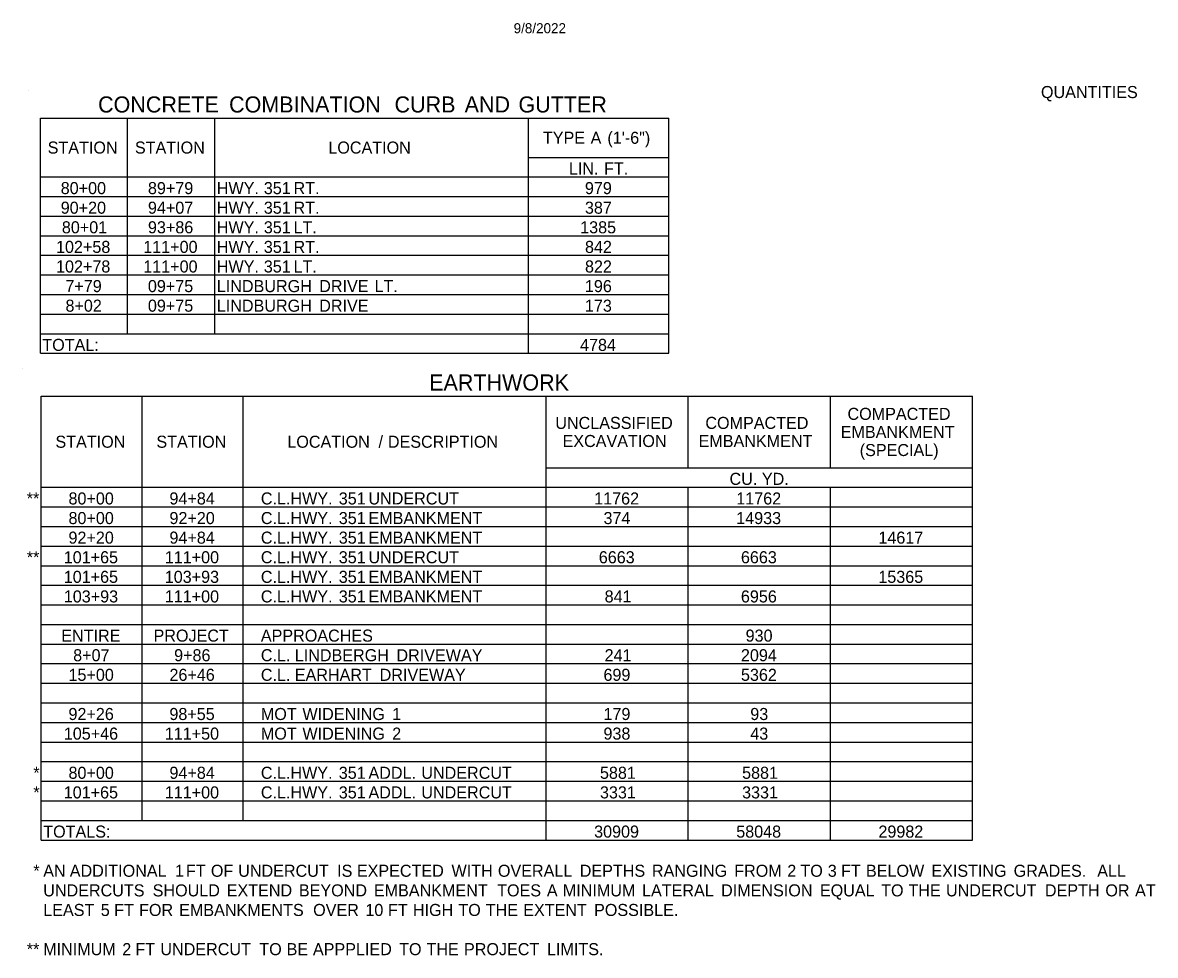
# Model space of a CAD drawing. Extents: x 1197542 to 1207068, y 230488 to 237324.
# Drawn here: x 1202654 to 1203218, y 232279 to 232744 of the extents above; entities that cross this region are included whole.
import ezdxf

# ---------------------------------------------------------------- set-up
doc = ezdxf.new("R2010")
doc.units = 0
doc.layers.add('Default', color=7, linetype='Continuous')
doc.layers.add('R_Border', color=7, linetype='Continuous')

msp = doc.modelspace()

# ---------------------------------------------------------------- linework, layer by layer
at = {"layer": 'Default'}
for p, q in [((1202657.22, 232709.68), (1202657.22, 232709.68)), ((1202663.07, 232696.03), (1202975.55, 232696.03)), ((1202663.07, 232579.03), (1202663.07, 232696.03)), ((1202663.07, 232579.03), (1202663.07, 232696.03)), ((1202706.45, 232588.78), (1202706.45, 232696.03)), ((1202749.84, 232588.78), (1202749.84, 232696.03)), ((1202905.84, 232579.03), (1202905.84, 232696.03)), ((1202975.55, 232579.03), (1202975.55, 232696.03)), ((1202905.84, 232676.53), (1202975.55, 232676.53)), ((1202663.07, 232666.78), (1202975.55, 232666.78)), ((1202706.45, 232588.78), (1202706.45, 232666.78)), ((1202749.84, 232588.78), (1202749.84, 232666.78)), ((1202905.84, 232666.78), (1202975.55, 232666.78)), ((1202905.84, 232579.03), (1202905.84, 232666.78)), ((1202663.07, 232657.03), (1202975.55, 232657.03)), ((1202749.84, 232657.03), (1202905.84, 232657.03)), ((1202663.07, 232647.28), (1202975.55, 232647.28)), ((1202663.07, 232637.53), (1202975.55, 232637.53)), ((1202663.07, 232627.78), (1202975.55, 232627.78)), ((1202663.07, 232618.03), (1202975.55, 232618.03)), ((1202663.07, 232608.28), (1202975.55, 232608.28)), ((1202663.07, 232598.53), (1202975.55, 232598.53)), ((1202663.07, 232588.78), (1202975.55, 232588.78)), ((1202975.55, 232579.03), (1202975.55, 232588.78)), ((1202663.07, 232579.03), (1202975.55, 232579.03)), ((1202654.25, 232571.35), (1202654.25, 232571.35)), ((1202663.52, 232557.7), (1203126.64, 232557.7)), ((1202663.52, 232336.86), (1202663.52, 232557.7)), ((1202663.52, 232336.86), (1202663.52, 232557.7)), ((1202713.73, 232346.61), (1202713.73, 232557.7)), ((1202763.94, 232346.61), (1202763.94, 232557.7)), ((1202914.58, 232336.86), (1202914.58, 232557.7)), ((1202985.27, 232522.11), (1202985.27, 232557.7)), ((1203055.95, 232522.11), (1203055.95, 232557.7)), ((1203126.64, 232336.86), (1203126.64, 232557.7)), ((1203126.64, 232336.86), (1203126.64, 232557.7)), ((1202914.58, 232522.11), (1203126.64, 232522.11)), ((1202663.52, 232512.36), (1203126.64, 232512.36)), ((1202713.73, 232346.61), (1202713.73, 232512.36)), ((1202763.94, 232502.61), (1202763.94, 232512.36)), ((1202914.58, 232502.61), (1202914.58, 232512.36)), ((1202985.27, 232336.86), (1202985.27, 232512.36)), ((1203055.95, 232336.86), (1203055.95, 232512.36)), ((1203055.95, 232346.61), (1203055.95, 232512.36)), ((1202663.52, 232502.61), (1203126.64, 232502.61)), ((1202663.52, 232492.86), (1203126.64, 232492.86)), ((1202663.52, 232483.11), (1203126.64, 232483.11)), ((1202763.94, 232346.61), (1202763.94, 232483.11)), ((1202914.58, 232375.86), (1202914.58, 232483.11)), ((1202663.52, 232473.36), (1203126.64, 232473.36)), ((1202663.52, 232463.61), (1203126.64, 232463.61)), ((1202663.52, 232453.86), (1203126.64, 232453.86)), ((1202663.52, 232444.11), (1203126.64, 232444.11)), ((1202663.52, 232434.36), (1203126.64, 232434.36)), ((1202663.52, 232424.61), (1203126.64, 232424.61)), ((1202663.52, 232414.86), (1203126.64, 232414.86)), ((1202663.52, 232405.11), (1203126.64, 232405.11)), ((1202663.52, 232395.36), (1203126.64, 232395.36)), ((1202663.52, 232385.61), (1203126.64, 232385.61)), ((1202663.52, 232375.86), (1203126.64, 232375.86)), ((1202713.73, 232375.86), (1202985.27, 232375.86)), ((1202985.27, 232375.86), (1203126.64, 232375.86)), ((1202663.52, 232366.11), (1203126.64, 232366.11)), ((1202663.52, 232356.36), (1203126.64, 232356.36)), ((1202914.58, 232346.61), (1202914.58, 232356.36)), ((1202663.52, 232346.61), (1202713.73, 232346.61)), ((1202663.52, 232346.61), (1203126.64, 232346.61)), ((1203055.95, 232346.61), (1203126.64, 232346.61)), ((1202663.52, 232336.86), (1203126.64, 232336.86))]:
    msp.add_line(p, q, dxfattribs=at)

# ---------------------------------------------------------------- texts
for s, height, p in [('CONCRETE', 8, (1202691.76, 232698.85)), (' COMBINATION', 8, (1202753.93, 232698.85)), (' CURB', 8, (1202836.24, 232698.85)), (' AND', 8, (1202871.09, 232698.85)), (' GUTTER', 8, (1202897.86, 232698.85)), ('TYPE', 6, (1202913.01, 232683.28)), (' A', 6, (1202934.49, 232683.28)), (' (1\'-6")', 6, (1202942.84, 232683.28)), ('STATION', 6, (1202666.7, 232678.4)), ('STATION', 6, (1202710.09, 232678.4)), ('LOCATION', 6, (1202806.29, 232678.4)), ('LIN.', 6, (1202925.91, 232667.98)), (' FT.', 6, (1202941.16, 232667.98)), ('80+00', 6, (1202673.19, 232658.23)), ('89+79', 6, (1202716.57, 232658.23)), ('HWY.', 6, (1202750.82, 232658.23)), (' 351', 6, (1202771.97, 232658.23)), (' RT.', 6, (1202786.74, 232658.23)), ('979', 6, (1202933.89, 232658.23)), ('90+20', 6, (1202673.19, 232648.48)), ('94+07', 6, (1202716.57, 232648.48)), ('HWY.', 6, (1202750.82, 232648.48)), (' 351', 6, (1202771.97, 232648.48)), (' RT.', 6, (1202786.74, 232648.48)), ('387', 6, (1202933.9, 232648.48)), ('80+01', 6, (1202673.76, 232638.73)), ('93+86', 6, (1202716.57, 232638.73)), ('HWY.', 6, (1202750.82, 232638.73)), (' 351', 6, (1202771.97, 232638.73)), (' LT.', 6, (1202786.74, 232638.73)), ('1385', 6, (1202931.54, 232638.73)), ('102+58', 6, (1202670.85, 232628.98)), ('111+00', 6, (1202714.25, 232628.98)), ('HWY.', 6, (1202750.82, 232628.98)), (' 351', 6, (1202771.97, 232628.98)), (' RT.', 6, (1202786.74, 232628.98)), ('842', 6, (1202933.93, 232628.98)), ('102+78', 6, (1202670.85, 232619.23)), ('111+00', 6, (1202714.25, 232619.23)), ('HWY.', 6, (1202750.82, 232619.23)), (' 351', 6, (1202771.97, 232619.23)), (' LT.', 6, (1202786.74, 232619.23)), ('822', 6, (1202933.93, 232619.23)), ('7+79', 6, (1202675.51, 232609.48)), ('09+75', 6, (1202716.55, 232609.48)), ('LINDBURGH', 6, (1202750.82, 232609.48)), (' DRIVE', 6, (1202799.52, 232609.48)), (' LT.', 6, (1202827.02, 232609.48)), ('196', 6, (1202933.9, 232609.48)), ('8+02', 6, (1202675.55, 232599.73)), ('09+75', 6, (1202716.55, 232599.73)), ('LINDBURGH', 6, (1202750.82, 232599.73)), (' DRIVE', 6, (1202799.52, 232599.73)), ('173', 6, (1202933.9, 232599.73)), ('TOTAL:', 6, (1202664.04, 232580.23)), ('4784', 6, (1202931.47, 232580.23)), ('EARTHWORK', 8, (1202856.43, 232560.52)), ('COMPACTED', 6, (1203064.49, 232545.9)), ('UNCLASSIFIED', 6, (1202919.16, 232541.4)), ('COMPACTED', 6, (1202993.8, 232541.4)), ('EMBANKMENT', 6, (1203061.11, 232536.9)), ('STATION', 6, (1202670.56, 232532.03)), ('STATION', 6, (1202720.77, 232532.03)), ('LOCATION', 6, (1202785.9, 232532.03)), (' /', 6, (1202829.01, 232532.03)), (' DESCRIPTION', 6, (1202833.67, 232532.03)), ('EXCAVATION', 6, (1202922.77, 232532.4)), ('EMBANKMENT', 6, (1202990.42, 232532.4)), ('(SPECIAL)', 6, (1203070.56, 232527.9)), ('CU.', 6, (1203005.82, 232513.56)), (' YD.', 6, (1203019.68, 232513.56)), ('**', 6, (1202656.31, 232503.81)), ('80+00', 6, (1202677.06, 232503.81)), ('94+84', 6, (1202727.27, 232503.81)), ('C.L.HWY.', 6, (1202772.72, 232503.81)), (' 351', 6, (1202809.24, 232503.81)), (' UNDERCUT', 6, (1202824.01, 232503.81)), ('11762', 6, (1202938.5, 232503.81)), ('11762', 6, (1203009.18, 232503.81)), ('80+00', 6, (1202677.06, 232494.06)), ('92+20', 6, (1202727.27, 232494.06)), ('C.L.HWY.', 6, (1202772.72, 232494.06)), (' 351', 6, (1202809.24, 232494.06)), (' EMBANKMENT', 6, (1202824.01, 232494.06)), ('374', 6, (1202943.14, 232494.06)), ('14933', 6, (1203009.15, 232494.06)), ('92+20', 6, (1202677.06, 232484.31)), ('94+84', 6, (1202727.27, 232484.31)), ('C.L.HWY.', 6, (1202772.72, 232484.31)), (' 351', 6, (1202809.24, 232484.31)), (' EMBANKMENT', 6, (1202824.01, 232484.31)), ('14617', 6, (1203079.84, 232484.31)), ('**', 6, (1202656.31, 232474.56)), ('101+65', 6, (1202674.69, 232474.56)), ('111+00', 6, (1202724.94, 232474.56)), ('C.L.HWY.', 6, (1202772.72, 232474.56)), (' 351', 6, (1202809.24, 232474.56)), (' UNDERCUT', 6, (1202824.01, 232474.56)), ('6663', 6, (1202940.79, 232474.56)), ('6663', 6, (1203011.48, 232474.56)), ('101+65', 6, (1202674.69, 232464.81)), ('103+93', 6, (1202724.93, 232464.81)), ('C.L.HWY.', 6, (1202772.72, 232464.81)), (' 351', 6, (1202809.24, 232464.81)), (' EMBANKMENT', 6, (1202824.01, 232464.81)), ('15365', 6, (1203079.82, 232464.81)), ('103+93', 6, (1202674.72, 232455.06)), ('111+00', 6, (1202724.94, 232455.06)), ('C.L.HWY.', 6, (1202772.72, 232455.06)), (' 351', 6, (1202809.24, 232455.06)), (' EMBANKMENT', 6, (1202824.01, 232455.06)), ('841', 6, (1202943.7, 232455.06)), ('6956', 6, (1203011.48, 232455.06)), ('ENTIRE', 6, (1202673.47, 232435.56)), ('PROJECT', 6, (1202719.35, 232435.56)), ('APPROACHES', 6, (1202772.72, 232435.56)), ('930', 6, (1203013.82, 232435.56)), ('8+07', 6, (1202679.38, 232425.81)), ('9+86', 6, (1202729.59, 232425.81)), ('C.L.', 6, (1202772.72, 232425.81)), (' LINDBERGH', 6, (1202787.36, 232425.81)), (' DRIVEWAY', 6, (1202837.92, 232425.81)), ('241', 6, (1202943.7, 232425.81)), ('2094', 6, (1203011.49, 232425.81)), ('15+00', 6, (1202677.06, 232416.06)), ('26+46', 6, (1202727.26, 232416.06)), ('C.L.', 6, (1202772.72, 232416.06)), (' EARHART', 6, (1202787.36, 232416.06)), (' DRIVEWAY', 6, (1202829.58, 232416.06)), ('699', 6, (1202943.12, 232416.06)), ('5362', 6, (1203011.51, 232416.06)), ('92+26', 6, (1202677.05, 232396.56)), ('98+55', 6, (1202727.24, 232396.56)), ('MOT', 6, (1202772.72, 232396.56)), (' WIDENING', 6, (1202791.17, 232396.56)), (' 1', 6, (1202835.82, 232396.56)), ('179', 6, (1202943.12, 232396.56)), ('93', 6, (1203016.14, 232396.56)), ('105+46', 6, (1202674.72, 232386.81)), ('111+50', 6, (1202724.94, 232386.81)), ('MOT', 6, (1202772.72, 232386.81)), (' WIDENING', 6, (1202791.17, 232386.81)), (' 2', 6, (1202835.82, 232386.81)), ('938', 6, (1202943.12, 232386.81)), ('43', 6, (1203016.14, 232386.81)), ('*', 6, (1202659.57, 232367.31)), ('80+00', 6, (1202677.06, 232367.31)), ('94+84', 6, (1202727.27, 232367.31)), ('C.L.HWY.', 6, (1202772.72, 232367.31)), (' 351', 6, (1202809.24, 232367.31)), (' ADDL.', 6, (1202824.01, 232367.31)), (' UNDERCUT', 6, (1202850.3, 232367.31)), ('5881', 6, (1202941.37, 232367.31)), ('5881', 6, (1203012.06, 232367.31)), ('*', 6, (1202659.57, 232357.56)), ('101+65', 6, (1202674.69, 232357.56)), ('111+00', 6, (1202724.94, 232357.56)), ('C.L.HWY.', 6, (1202772.72, 232357.56)), (' 351', 6, (1202809.24, 232357.56)), (' ADDL.', 6, (1202824.01, 232357.56)), (' UNDERCUT', 6, (1202850.3, 232357.56)), ('3331', 6, (1202941.37, 232357.56)), ('3331', 6, (1203012.06, 232357.56)), ('TOTALS:', 6, (1202664.49, 232338.06)), ('30909', 6, (1202938.47, 232338.06)), ('58048', 6, (1203009.15, 232338.06)), ('29982', 6, (1203079.86, 232338.06)), ('*', 6, (1202659.57, 232318.56)), ('AN', 6, (1202664.49, 232318.56)), (' ADDITIONAL', 6, (1202675.45, 232318.56)), (' 1', 6, (1202727.79, 232318.56)), (' FT', 6, (1202733.24, 232318.56)), (' OF', 6, (1202745.64, 232318.56)), (' UNDERCUT', 6, (1202759.23, 232318.56)), (' IS', 6, (1202808.43, 232318.56)), (' EXPECTED', 6, (1202818.24, 232318.56)), (' WITH', 6, (1202865.32, 232318.56)), (' OVERALL', 6, (1202888.39, 232318.56)), (' DEPTHS', 6, (1202929.09, 232318.56)), (' RANGING', 6, (1202964.99, 232318.56)), (' FROM', 6, (1203005.92, 232318.56)), (' 2', 6, (1203032.3, 232318.56)), (' TO', 6, (1203038.84, 232318.56)), (' 3', 6, (1203052.44, 232318.56)), (' FT', 6, (1203059.05, 232318.56)), (' BELOW', 6, (1203071.45, 232318.56)), (' EXISTING', 6, (1203103.96, 232318.56)), (' GRADES.', 6, (1203144.89, 232318.56)), ('  ALL', 6, (1203184.23, 232318.56)), ('UNDERCUTS', 6, (1202664.49, 232308.81)), (' SHOULD', 6, (1202716.69, 232308.81)), (' EXTEND', 6, (1202753.51, 232308.81)), (' BEYOND', 6, (1202789.4, 232308.81)), (' EMBANKMENT', 6, (1202826.69, 232308.81)), (' TOES', 6, (1202888.01, 232308.81)), (' A', 6, (1202912.73, 232308.81)), (' MINIMUM', 6, (1202920.66, 232308.81)), (' LATERAL', 6, (1202960.07, 232308.81)), (' DIMENSION', 6, (1202999.38, 232308.81)), (' EQUAL', 6, (1203048.53, 232308.81)), (' TO', 6, (1203078.99, 232308.81)), (' THE', 6, (1203092.58, 232308.81)), (' UNDERCUT', 6, (1203111.23, 232308.81)), (' DEPTH', 6, (1203160.43, 232308.81)), (' OR', 6, (1203190.5, 232308.81)), (' AT', 6, (1203205.29, 232308.81)), ('LEAST', 6, (1202664.49, 232299.06)), (' 5', 6, (1202690.88, 232299.06)), (' FT', 6, (1202697.54, 232299.06)), (' FOR', 6, (1202709.94, 232299.06)), (' EMBANKMENTS', 6, (1202729.85, 232299.06)), (' OVER', 6, (1202796.5, 232299.06)), (' 10', 6, (1202822.47, 232299.06)), (' FT', 6, (1202833.72, 232299.06)), (' HIGH', 6, (1202846.12, 232299.06)), (' TO', 6, (1202868.73, 232299.06)), (' THE', 6, (1202882.33, 232299.06)), (' EXTENT', 6, (1202900.98, 232299.06)), (' POSSIBLE.', 6, (1202936.21, 232299.06)), ('**', 6, (1202656.31, 232279.56)), ('MINIMUM', 6, (1202664.49, 232279.56)), (' 2', 6, (1202701.58, 232279.56)), (' FT', 6, (1202708.12, 232279.56)), (' UNDERCUT', 6, (1202720.52, 232279.56)), (' TO', 6, (1202769.73, 232279.56)), (' BE', 6, (1202783.32, 232279.56)), (' APPPLIED', 6, (1202796.39, 232279.56)), (' TO', 6, (1202839.27, 232279.56)), (' THE', 6, (1202852.87, 232279.56)), (' PROJECT', 6, (1202871.52, 232279.56)), (' LIMITS.', 6, (1202912.81, 232279.56))]:
    msp.add_text(s, height=height, dxfattribs=at).set_placement(p)
at = {"layer": 'R_Border'}
for s, height, p in [('9/8/2022', 5, (1202898.45, 232738.29)), ('QUANTITIES', 6, (1203160.7, 232706.03))]:
    msp.add_text(s, height=height, rotation=360, dxfattribs=at).set_placement(p)

doc.saveas('drawing.dxf')
